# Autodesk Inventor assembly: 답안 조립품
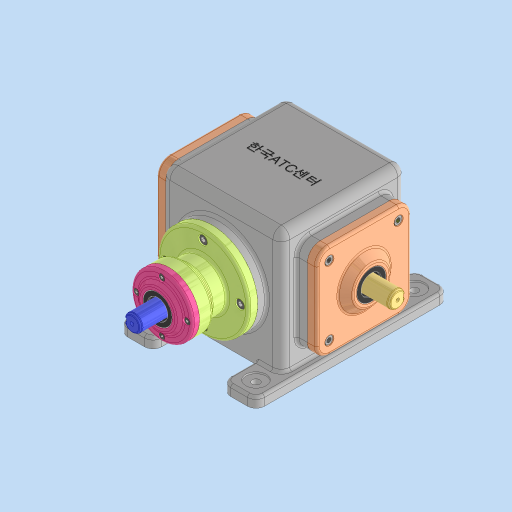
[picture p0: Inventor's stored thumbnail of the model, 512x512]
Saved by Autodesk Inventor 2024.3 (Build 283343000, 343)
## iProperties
Created: 2026-01
Part Number: 답안 조립품
Document SubType Name: Assembly
Designer: PC2-02
Author: PC2-02
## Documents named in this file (16)
- C:\Users\PC2-02\Desktop\760103V1006\답안 조립품.iam
- C:\Users\PC2-02\Desktop\760103V1006\본체.ipt
- C:\Users\PC2-02\Desktop\760103V1006\종동축\종동축.ipt
- C:\Users\PC2-02\Desktop\760103V1006\측면 커버\측면 커버.ipt
- C:\Users\PC2-02\Desktop\760103V1006\오일 실 20 35 8\오일 실 20 35 8.ipt
- C:\Users\PC2-02\Desktop\760103V1006\테이퍼 롤러 베어링 30204K\테이퍼 롤러 베어링 30204K.ipt
- C:\Users\PC2-02\Desktop\760103V1006\칼라\칼라.ipt
- C:\Users\PC2-02\Desktop\760103V1006\평행 키 6x6x18\평행 키 6x6x18.ipt
- C:\Users\PC2-02\Desktop\760103V1006\베벨 기어(종동)\베벨 기어(종동).ipt
- C:\Users\PC2-02\Desktop\760103V1006\구동축\구동축.ipt
- C:\Users\PC2-02\Desktop\760103V1006\베어링 하우징\베어링 하우징.ipt
- C:\Users\PC2-02\Desktop\760103V1006\베벨 기어(구동)\베벨 기어(구동).ipt
- C:\Users\PC2-02\Desktop\760103V1006\엔드캡\엔드캡.ipt
- C:\Users\PC2-02\Desktop\760103V1006\6각 구멍붙이 볼트 M6x12\6각 구멍붙이 볼트 M6x12.ipt
- C:\Users\PC2-02\Desktop\760103V1006\하우징 커버\하우징 커버.ipt
- C:\Users\PC2-02\Desktop\760103V1006\6각 구멍붙이 볼트 M4x10\6각 구멍붙이 볼트 M4x10.ipt
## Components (19 placed, 4 different names)
1. 구동축:1
2. 6각 구멍붙이 볼트 M6x12:1
3. 6각 구멍붙이 볼트 M6x12:2
4. 6각 구멍붙이 볼트 M6x12:3
5. 6각 구멍붙이 볼트 M6x12:4
6. 하우징 커버:1
7. 6각 구멍붙이 볼트 M4x10:1
8. 6각 구멍붙이 볼트 M4x10:2
9. 6각 구멍붙이 볼트 M4x10:3
10. 6각 구멍붙이 볼트 M4x10:4
11. 6각 구멍붙이 볼트 M6x12:5
12. 6각 구멍붙이 볼트 M6x12:7
13. 6각 구멍붙이 볼트 M6x12:8
14. 6각 구멍붙이 볼트 M6x12:9
15. 6각 구멍붙이 볼트 M6x12:13
16. 6각 구멍붙이 볼트 M6x12:6
17. 6각 구멍붙이 볼트 M6x12:10
18. 6각 구멍붙이 볼트 M6x12:11
19. 6각 구멍붙이 볼트 M6x12:12
